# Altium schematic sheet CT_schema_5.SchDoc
size 329 x 334 mm
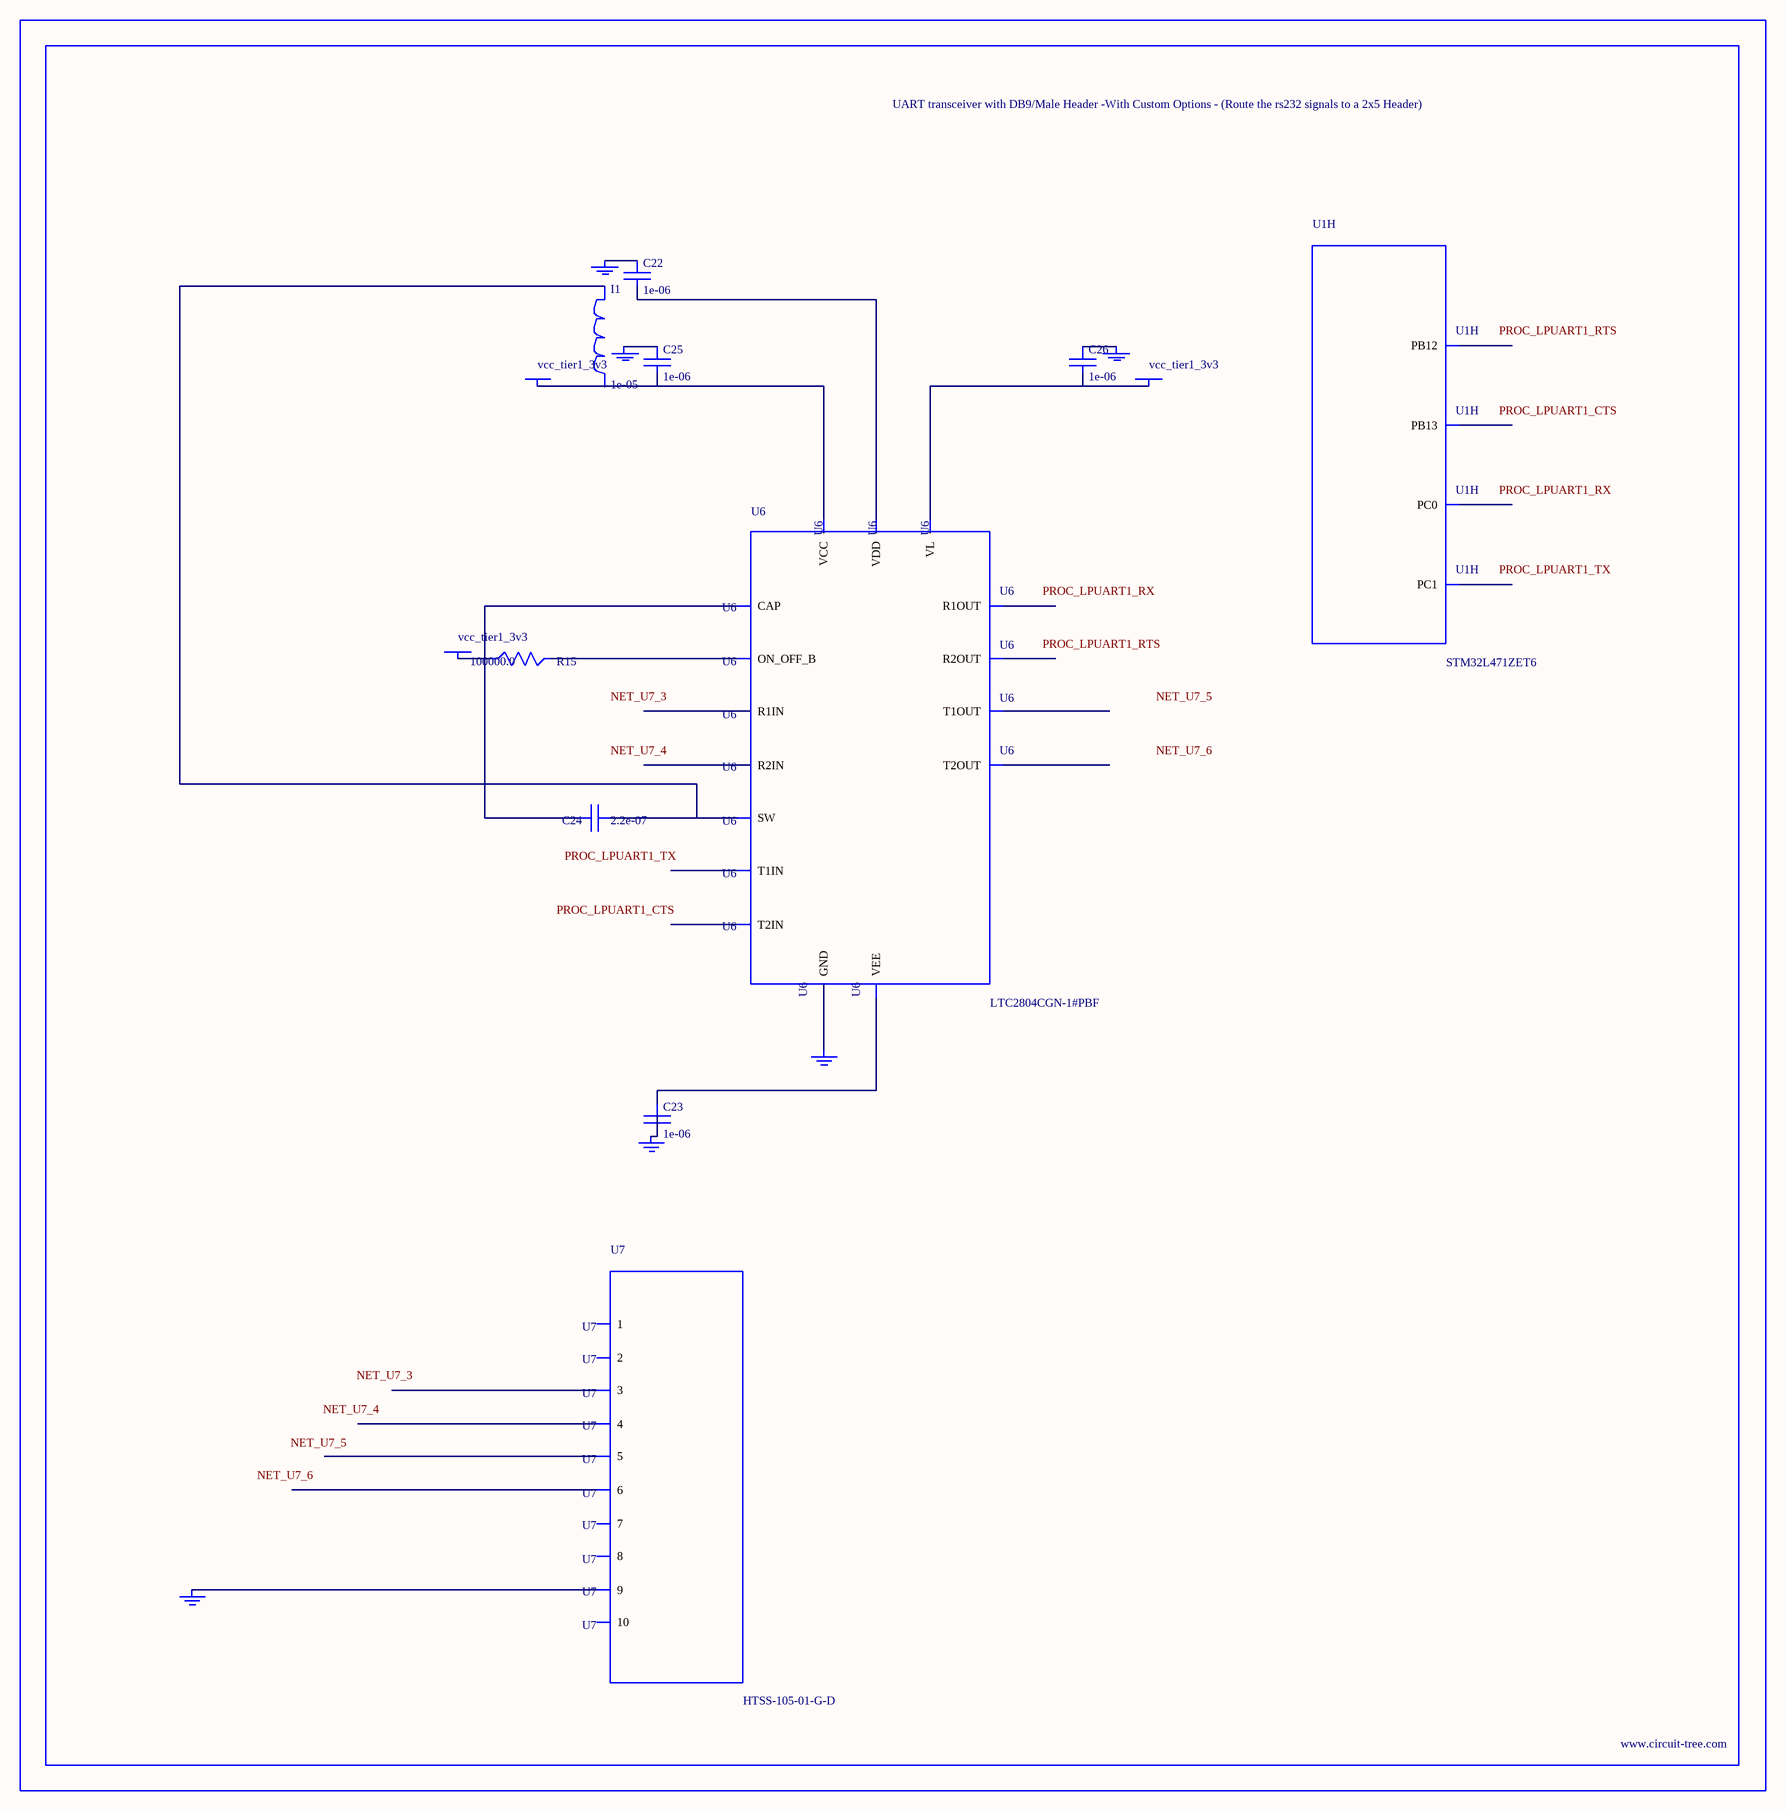
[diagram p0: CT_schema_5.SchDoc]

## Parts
BORDER4  (no value)
C22  1e-06  [C0603]
C23  1e-06  [C0603]
C24  2.2e-07  [C0603]
C25  1e-06  [C0603]
C26  1e-06  [C0603]
GND_INSTANCE_4_0  (no value)
GND_INSTANCE_4_1  (no value)
GND_INSTANCE_4_2  (no value)
GND_INSTANCE_4_3  (no value)
GND_INSTANCE_4_4  (no value)
GND_INSTANCE_4_5  (no value)
I1  1e-05  [L1210]
POWER_INSTANCE_4_0  vcc_tier1_3v3
POWER_INSTANCE_4_1  vcc_tier1_3v3
POWER_INSTANCE_4_2  vcc_tier1_3v3
R15  100000.0  [R0603]
U1  STM32L471ZET6  [LQFP144]  (part H of 13)
U6  LTC2804CGN-1#PBF  [SSOP-16]
U7  HTSS-105-01-G-D  [HTSS-105-01-G-D]

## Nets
NetC22_1: C22.1 GND_INSTANCE_4_1.0(GND)
NetC22_2: C22.2 U6.6(VDD)
NetC23_1: C23.1 U6.9(VEE)
NetC23_2: C23.2 GND_INSTANCE_4_2.0(GND)
NetC24_1: C24.1 I1.1 U6.7(SW)
NetC24_2: C24.2 U6.10(CAP)
NetC25_1: C25.1 GND_INSTANCE_4_0.0(GND)
NetC25_2: C25.2 POWER_INSTANCE_4_0.0(PWR) U6.5(VCC)
NetC26_1: C26.1 GND_INSTANCE_4_3.0(GND)
NetC26_2: C26.2 POWER_INSTANCE_4_2.0(PWR) U6.12(VL)
NetGND_INSTANCE_4_4_0: GND_INSTANCE_4_4.0(GND) U6.8(GND)
NetGND_INSTANCE_4_5_0: GND_INSTANCE_4_5.0(GND) U7.9
NetPOWER_INSTANCE_4_1_0: POWER_INSTANCE_4_1.0(PWR) R15.1
NetR15_2: R15.2 U6.11(ON_OFF_B)

Not connected (* = marked no-connect by the designer): I1 2; U1 26(PC0) 27(PC1) 73(PB12) 74(PB13); U6 1(R1IN) 2(R2IN) 3(T1OUT) 4(T2OUT) 13(T2IN) 14(T1IN) 15(R2OUT) 16(R1OUT); U7 1 2 3 4 5 6 7 8 10

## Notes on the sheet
- Labels drawn without touching a wire or pin: NET_U7_3, NET_U7_4, NET_U7_5, NET_U7_6, PROC_LPUART1_CTS, PROC_LPUART1_RTS, PROC_LPUART1_RX, PROC_LPUART1_TX

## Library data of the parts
BORDER4 = BORDER_PAGE4
C22 C23 C25 C26 = C0603C105K3RACTU
C24 = C0603C224K3RAC
GND_INSTANCE_4_0-GND_INSTANCE_4_5 = GND
I1 = CBC3225T100MR
POWER_INSTANCE_4_0-POWER_INSTANCE_4_2 = PWR
R15 = RC0603JR-07100KL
